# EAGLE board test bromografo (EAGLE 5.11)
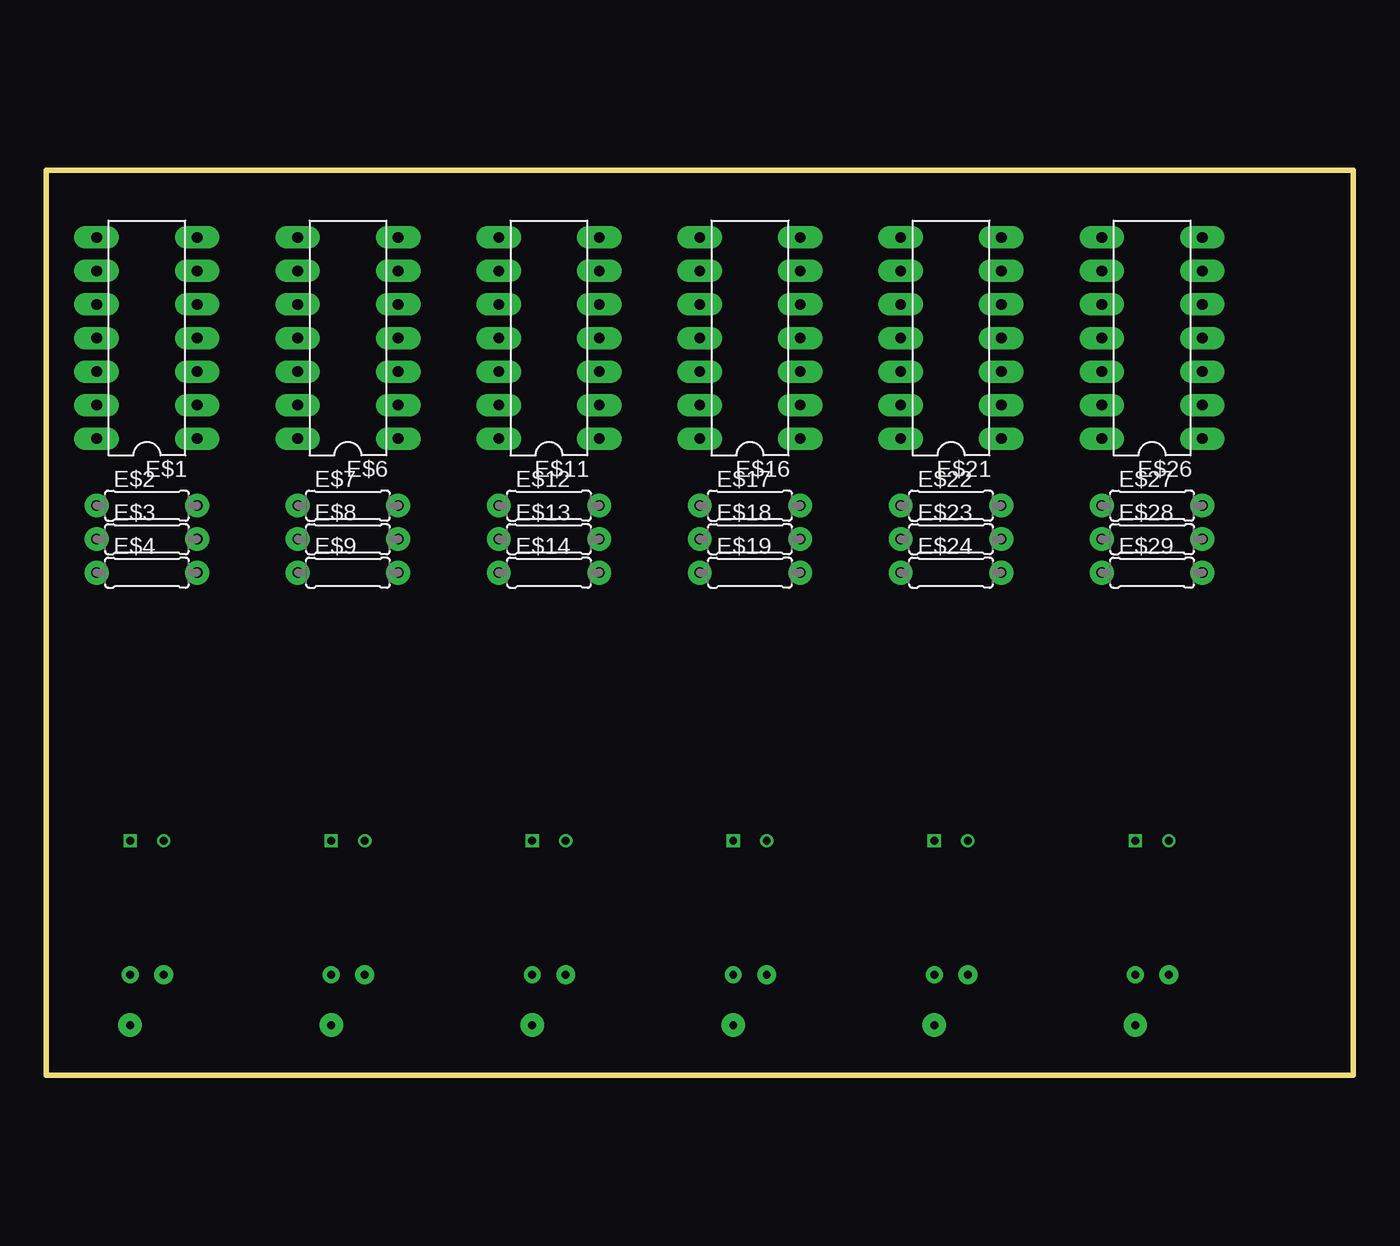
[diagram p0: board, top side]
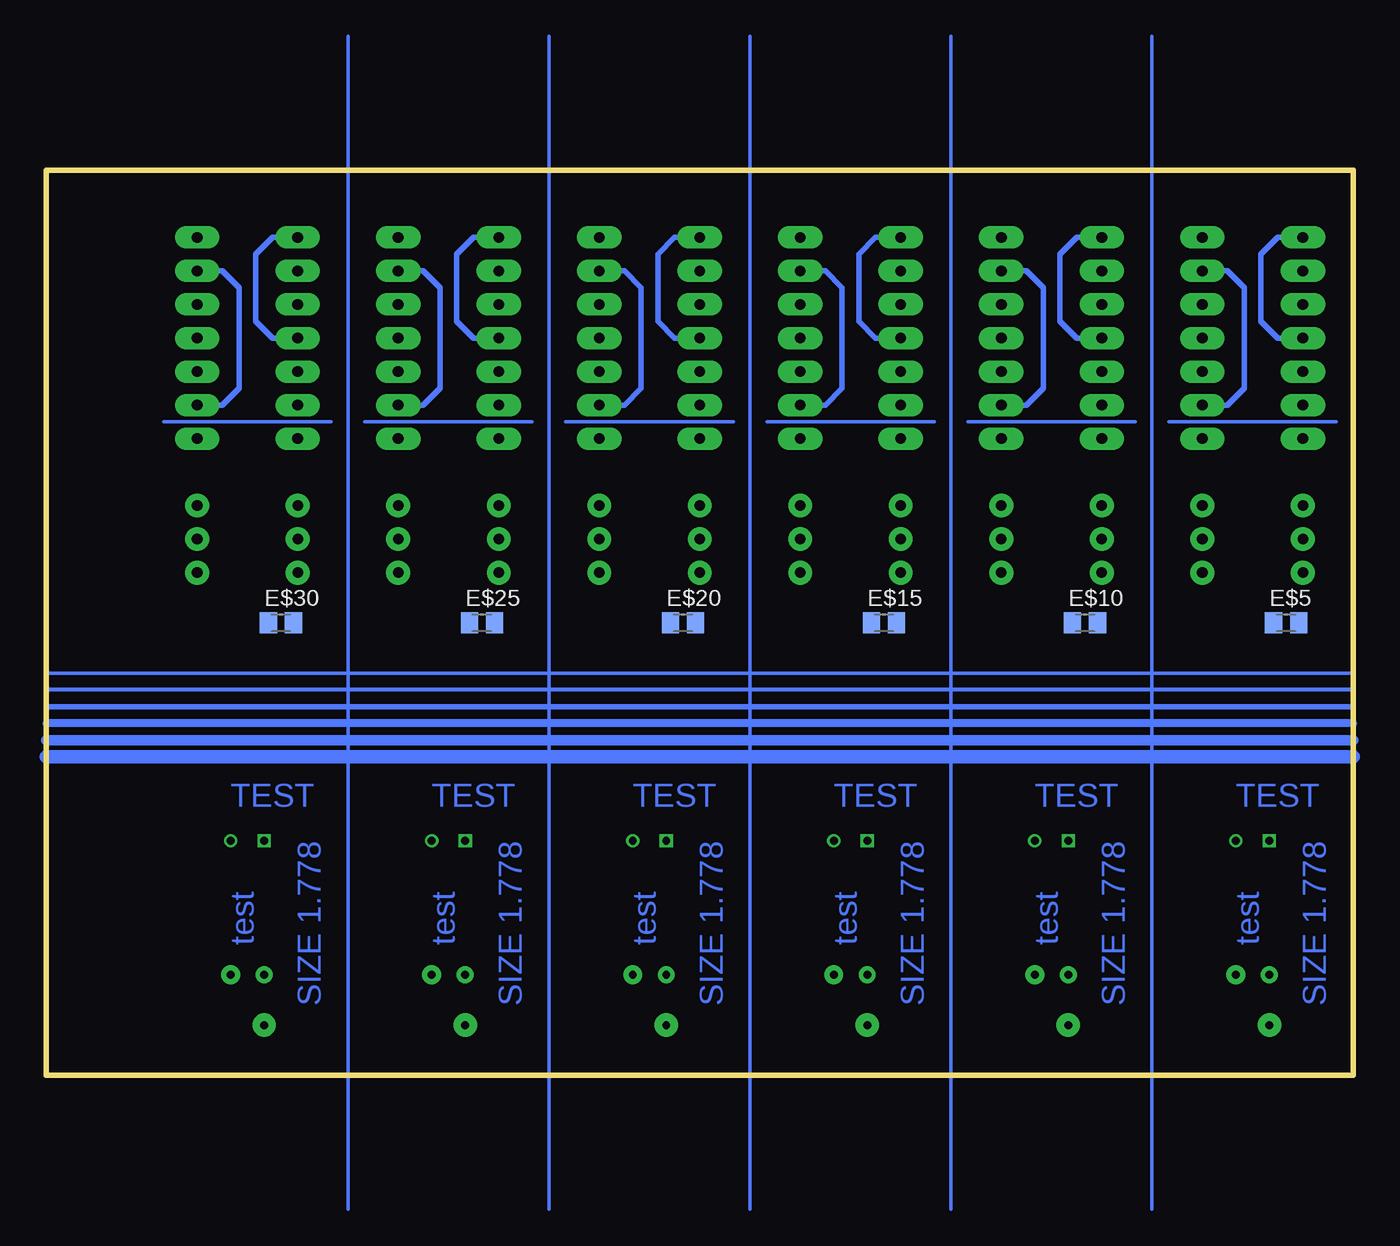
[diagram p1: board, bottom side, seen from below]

Size 99.06 x 68.58 mm. Coordinates in mm from the lower left corner, seen from the top.
Outline: 99.06,0 99.06,68.58 0,68.58 0,0 12.7,0 25.4,0 99.06,0
Copper layers (1*16): Top 0.035mm / dielectric 1.5mm / Bottom 0.035mm
Design rules "default": minimum track width 10mil, minimum drill 24mil, track to track 8mil, track to pad 8mil, pad to pad 8mil, via to via 8mil, smd to smd 8mil, copper to edge 40mil, drill to drill 8mil, minimum pad ring 10mil, minimum via ring 8mil, stop-mask expansion 4mil, vias tented up to drill 0mil, thermal gap 10mil

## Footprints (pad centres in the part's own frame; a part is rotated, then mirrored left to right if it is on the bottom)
DIL14 = drill 0.813 pad 1.7 long: 1 -7.62,-3.81; 2 -5.08,-3.81; 3 -2.54,-3.81; 4 0,-3.81; 5 2.54,-3.81; 6 5.08,-3.81; 7 7.62,-3.81; 8 7.62,3.81; 9 5.08,3.81; 10 2.54,3.81; 11 0,3.81; 12 -2.54,3.81; 13 -5.08,3.81; 14 -7.62,3.81
0207/7 = drill 0.8 pad 1.8 round: 1 -3.81,0; 2 3.81,0
M0805 = smd 1.3 x 1.6: 1 -0.95,0; 2 0.95,0

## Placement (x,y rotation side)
E$1  [DIL14]  7.62,55.88 90 top
E$2  [0207/7]  7.62,43.18 0 top
E$3  [0207/7]  7.62,40.64 0 top
E$4  [0207/7]  7.62,38.1 0 top
E$5  [M0805]  5.08,34.29 0 bottom
E$6  [DIL14]  22.86,55.88 90 top
E$7  [0207/7]  22.86,43.18 0 top
E$8  [0207/7]  22.86,40.64 0 top
E$9  [0207/7]  22.86,38.1 0 top
E$10  [M0805]  20.32,34.29 0 bottom
E$11  [DIL14]  38.1,55.88 90 top
E$12  [0207/7]  38.1,43.18 0 top
E$13  [0207/7]  38.1,40.64 0 top
E$14  [0207/7]  38.1,38.1 0 top
E$15  [M0805]  35.56,34.29 0 bottom
E$16  [DIL14]  53.34,55.88 90 top
E$17  [0207/7]  53.34,43.18 0 top
E$18  [0207/7]  53.34,40.64 0 top
E$19  [0207/7]  53.34,38.1 0 top
E$20  [M0805]  50.8,34.29 0 bottom
E$21  [DIL14]  68.58,55.88 90 top
E$22  [0207/7]  68.58,43.18 0 top
E$23  [0207/7]  68.58,40.64 0 top
E$24  [0207/7]  68.58,38.1 0 top
E$25  [M0805]  66.04,34.29 0 bottom
E$26  [DIL14]  83.82,55.88 90 top
E$27  [0207/7]  83.82,43.18 0 top
E$28  [0207/7]  83.82,40.64 0 top
E$29  [0207/7]  83.82,38.1 0 top
E$30  [M0805]  81.28,34.29 0 bottom

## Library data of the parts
E$1 E$6 E$11 E$16 E$21 E$26 = #-microchip
E$2-E$5 E$7-E$10 E$12-E$15 E$17-E$20 E$22-E$25 E$27-E$30 = #-rcl

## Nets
S$1: E$1.8 E$1.11
S$2: E$1.2 E$1.6
S$16: E$6.8 E$6.11
S$17: E$6.2 E$6.6
S$25: E$11.8 E$11.11
S$26: E$11.2 E$11.6
S$34: E$16.8 E$16.11
S$35: E$16.2 E$16.6
S$43: E$21.8 E$21.11
S$44: E$21.2 E$21.6
S$52: E$26.8 E$26.11
S$53: E$26.2 E$26.6

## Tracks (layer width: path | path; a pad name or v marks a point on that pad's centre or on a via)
S$1
  Bottom 0.406: E$1.8 5.71,63.5 6.99,62.23 6.99,57.15 5.71,55.88 E$1.11
S$2
  Bottom 0.406: E$1.6 9.53,60.96 8.26,59.69 8.26,52.07 9.53,50.8 E$1.2
S$3
  Bottom 0.254: 1.27,49.53 13.97,49.53
S$4
  Bottom 0.254: 0,30.48 99.06,30.48
S$5
  Bottom 0.305: 0,29.21 99.06,29.21
S$6
  Bottom 0.406: 0,27.94 99.06,27.94
S$7
  Bottom 0.61: 0,26.67 99.06,26.67
S$8
  Bottom 0.813: 0,25.4 99.06,25.4
S$9
  Bottom 1.016: 0,24.13 99.06,24.13
S$10  (via drill 0.6)
  other vias: 6.35,17.78
S$11  (via drill 0.6 pad 1.02)
  other vias: 8.89,17.78
S$12  (via drill 0.6 pad 1.27)
  other vias: 6.35,7.62
S$13  (via drill 0.6 pad 1.42)
  other vias: 8.89,7.62
S$14  (via drill 0.6 pad 1.78)
  other vias: 6.35,3.81
S$15
  Bottom 0.254: 15.24,-10.16 15.24,78.74
S$16
  Bottom 0.406: E$6.8 20.95,63.5 22.23,62.23 22.23,57.15 20.95,55.88 E$6.11
S$17
  Bottom 0.406: E$6.6 24.77,60.96 23.5,59.69 23.5,52.07 24.77,50.8 E$6.2
S$18
  Bottom 0.254: 16.51,49.53 29.21,49.53
S$19  (via drill 0.6)
  other vias: 21.59,17.78
S$20  (via drill 0.6 pad 1.02)
  other vias: 24.13,17.78
S$21  (via drill 0.6 pad 1.27)
  other vias: 21.59,7.62
S$22  (via drill 0.6 pad 1.42)
  other vias: 24.13,7.62
S$23  (via drill 0.6 pad 1.78)
  other vias: 21.59,3.81
S$24
  Bottom 0.254: 30.48,-10.16 30.48,78.74
S$25
  Bottom 0.406: E$11.8 36.2,63.5 37.47,62.23 37.47,57.15 36.2,55.88 E$11.11
S$26
  Bottom 0.406: E$11.6 40.01,60.96 38.73,59.69 38.73,52.07 40.01,50.8 E$11.2
S$27
  Bottom 0.254: 31.75,49.53 44.45,49.53
S$28  (via drill 0.6)
  other vias: 36.83,17.78
S$29  (via drill 0.6 pad 1.02)
  other vias: 39.37,17.78
S$30  (via drill 0.6 pad 1.27)
  other vias: 36.83,7.62
S$31  (via drill 0.6 pad 1.42)
  other vias: 39.37,7.62
S$32  (via drill 0.6 pad 1.78)
  other vias: 36.83,3.81
S$33
  Bottom 0.254: 45.72,-10.16 45.72,78.74
S$34
  Bottom 0.406: E$16.8 51.44,63.5 52.7,62.23 52.7,57.15 51.44,55.88 E$16.11
S$35
  Bottom 0.406: E$16.6 55.24,60.96 53.98,59.69 53.98,52.07 55.24,50.8 E$16.2
S$36
  Bottom 0.254: 46.99,49.53 59.69,49.53
S$37  (via drill 0.6)
  other vias: 52.07,17.78
S$38  (via drill 0.6 pad 1.02)
  other vias: 54.61,17.78
S$39  (via drill 0.6 pad 1.27)
  other vias: 52.07,7.62
S$40  (via drill 0.6 pad 1.42)
  other vias: 54.61,7.62
S$41  (via drill 0.6 pad 1.78)
  other vias: 52.07,3.81
S$42
  Bottom 0.254: 60.96,-10.16 60.96,78.74
S$43
  Bottom 0.406: E$21.8 66.67,63.5 67.94,62.23 67.94,57.15 66.67,55.88 E$21.11
S$44
  Bottom 0.406: E$21.6 70.48,60.96 69.22,59.69 69.22,52.07 70.48,50.8 E$21.2
S$45
  Bottom 0.254: 62.23,49.53 74.93,49.53
S$46  (via drill 0.6)
  other vias: 67.31,17.78
S$47  (via drill 0.6 pad 1.02)
  other vias: 69.85,17.78
S$48  (via drill 0.6 pad 1.27)
  other vias: 67.31,7.62
S$49  (via drill 0.6 pad 1.42)
  other vias: 69.85,7.62
S$50  (via drill 0.6 pad 1.78)
  other vias: 67.31,3.81
S$51
  Bottom 0.254: 76.2,-10.16 76.2,78.74
S$52
  Bottom 0.406: E$26.8 81.92,63.5 83.19,62.23 83.19,57.15 81.92,55.88 E$26.11
S$53
  Bottom 0.406: E$26.6 85.72,60.96 84.45,59.69 84.45,52.07 85.72,50.8 E$26.2
S$54
  Bottom 0.254: 77.47,49.53 90.17,49.53
S$55  (via drill 0.6)
  other vias: 82.55,17.78
S$56  (via drill 0.6 pad 1.02)
  other vias: 85.09,17.78
S$57  (via drill 0.6 pad 1.27)
  other vias: 82.55,7.62
S$58  (via drill 0.6 pad 1.42)
  other vias: 85.09,7.62
S$59  (via drill 0.6 pad 1.78)
  other vias: 82.55,3.81

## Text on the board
Bottom: TEST | TEST | TEST | TEST | TEST | TEST | SIZE 1.778 | SIZE 1.778 | SIZE 1.778 | SIZE 1.778 | SIZE 1.778 | SIZE 1.778 | test | test | test | test | test | test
